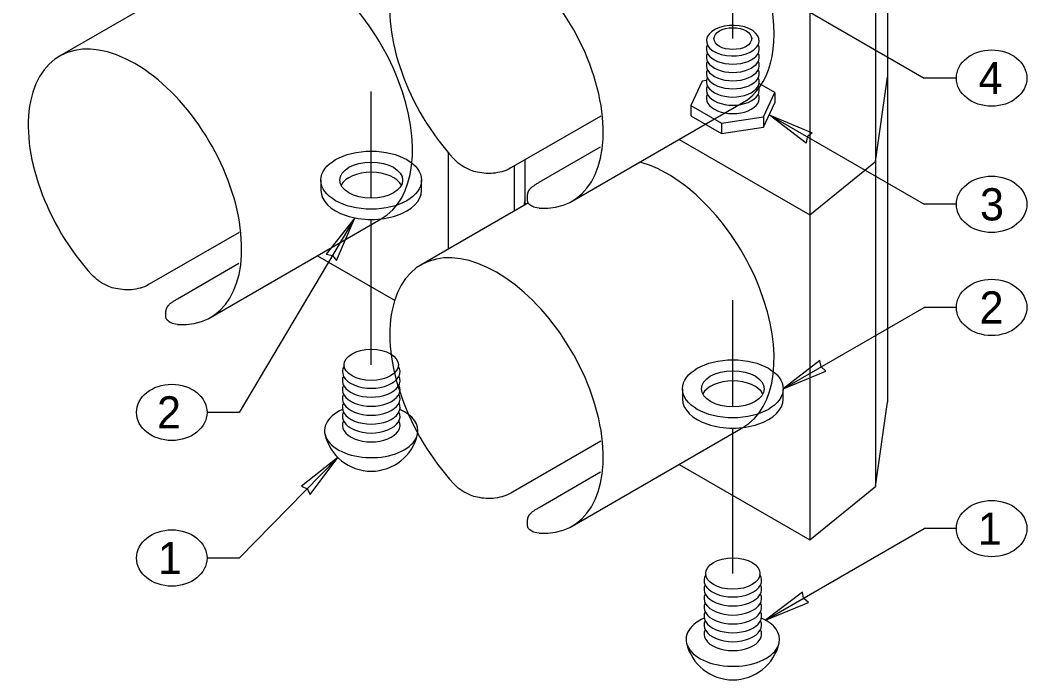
# Model space of a CAD drawing. Extents: x 99862 to 104211, y 98939 to 105076.
# Drawn here: x 101813 to 102313, y 100883 to 101211 of the extents above; entities that cross this region are included whole.
import ezdxf

# ---------------------------------------------------------------- set-up
doc = ezdxf.new("R2010")
doc.units = 0
for name, color, linetype in [('Level 1', 7, 'Continuous'), ('Level 15', 7, 'Continuous'), ('Level 19', 7, 'Continuous'), ('Level 2', 7, 'Continuous'), ('Level 20', 7, 'Continuous'), ('Level 26', 7, 'Continuous'), ('Level 3', 7, 'Continuous')]:
    doc.layers.add(name, color=color, linetype=linetype)

msp = doc.modelspace()

# ---------------------------------------------------------------- linework, layer by layer
at = {"layer": 'Level 1'}
for centre in [(101987.57, 101010.53), (102167.22, 100906.81)]:
    msp.add_arc(centre, 23.6, 192.7466, 347.2534, dxfattribs=at)
for centre in [(101987.57, 101039.77), (102167.22, 100936.05)]:
    msp.add_ellipse(centre, major_axis=(-13.49, 0), ratio=0.57735, dxfattribs=at)
for centre, major_axis, start_param, end_param in [((101987.57, 101036.43), (14.31, 0), 2.795302, 6.629476), ((101987.57, 101031.98), (14.31, 0), 2.86885, 6.555928), ((101987.57, 101027.44), (14.31, 0), 2.86338, 6.561398), ((101987.57, 101022.99), (14.31, 0), 2.86885, 6.555928), ((101987.57, 101007.06), (23.21, 0), 2.229419, 6.153315), ((101987.57, 101018.63), (14.31, 0), 2.874311, 6.550467), ((101987.57, 101007.06), (23.21, 0), 6.153315, 7.195359), ((101987.57, 101014.18), (14.31, 0), 2.86885, 6.555928), ((101987.57, 101009.73), (14.31, 0), 2.86885, 6.555928), ((102167.22, 100932.71), (14.31, 0), 2.795302, 6.629476), ((102167.22, 100928.26), (14.31, 0), 2.86885, 6.555928), ((102167.22, 100923.72), (14.31, 0), 2.86338, 6.561398), ((102167.22, 100919.27), (14.31, 0), 2.86885, 6.555928), ((102167.22, 100914.91), (14.31, 0), 2.874311, 6.550467), ((102167.22, 100903.34), (23.21, 0), 2.229419, 6.153315), ((102167.22, 100910.46), (14.31, 0), 2.86885, 6.555928), ((102167.22, 100903.34), (23.21, 0), 6.153315, 7.195359), ((102167.22, 100906.01), (14.31, 0), 2.86885, 6.555928)]:
    msp.add_ellipse(centre, major_axis=major_axis, ratio=0.57735, start_param=start_param, end_param=end_param, dxfattribs=at)
at = {"layer": 'Level 15'}
for p, q in [((102184.9, 101227.03), (102262.3, 101182.34)), ((102167.23, 101201.93), (102167.23, 101217.7)), ((102278.3, 101182.34), (102262.3, 101182.34)), ((101987.57, 101122.57), (101987.57, 101175.69)), ((102185.33, 101164.02), (102262.3, 101119.58)), ((102278.3, 101119.58), (102262.3, 101119.58)), ((101979.46, 101112.84), (101921.98, 101016.17)), ((101987.57, 101039.77), (101987.57, 101112.06)), ((102167.22, 101018.86), (102167.22, 101071.97)), ((102192.22, 101027.88), (102262.3, 101068.34)), ((102278.3, 101068.34), (102262.3, 101068.34)), ((101921.98, 101016.17), (101905.98, 101016.17)), ((102167.22, 100936.05), (102167.22, 101008.34)), ((101971.03, 100993.7), (101921.98, 100943.78)), ((102183.5, 100912.89), (102262.3, 100958.39)), ((102278.3, 100958.39), (102262.3, 100958.39)), ((101921.98, 100943.78), (101905.98, 100943.78))]:
    msp.add_line(p, q, dxfattribs=at)
for points in [[(102185.33, 101164.02), (102206.6, 101155.19), (102204.19, 101153.13), (102203.61, 101150.02)], [(101979.46, 101112.84), (101965.22, 101094.74), (101968.33, 101094.13), (101970.36, 101091.69)], [(102192.22, 101027.88), (102213.48, 101036.71), (102211.08, 101038.76), (102210.5, 101041.88)], [(101971.03, 100993.7), (101952.9, 100979.51), (101955.77, 100978.17), (101957.16, 100975.32)], [(102183.5, 100912.89), (102204.77, 100921.72), (102202.36, 100923.78), (102201.78, 100926.89)]]:
    msp.add_lwpolyline(points, close=True, dxfattribs=at)
at = {"layer": 'Level 19'}
for p, q in [((102238.16, 101140.84), (102244.04, 101182.83)), ((102205.4, 101114.35), (102238.16, 101140.84)), ((102063.56, 101119.06), (102063.98, 101122.03)), ((102238.16, 100979.28), (102244.04, 101021.28)), ((102205.4, 100952.79), (102238.16, 100979.28))]:
    msp.add_line(p, q, dxfattribs=at)
at = {"layer": 'Level 2'}
for p, q in [((102182.53, 101163.08), (102188.13, 101175.16)), ((102146.31, 101168.69), (102161.62, 101159.85)), ((102161.62, 101159.85), (102182.53, 101163.08)), ((102182.53, 101163.08), (102182.53, 101157.98)), ((102161.62, 101159.85), (102161.62, 101154.74)), ((101962.57, 101131.59), (101962.57, 101126.49)), ((102012.57, 101126.49), (102012.57, 101131.59)), ((102142.22, 101027.88), (102142.22, 101022.77)), ((102192.22, 101022.77), (102192.22, 101027.88))]:
    msp.add_line(p, q, dxfattribs=at)
for centre, major_axis in [((102167.22, 101201.93), (9.38, 0)), ((101987.57, 101131.59), (25, 0)), ((101987.57, 101131.59), (15.62, 0)), ((102167.22, 101027.88), (25, 0)), ((102167.22, 101027.88), (15.62, 0))]:
    msp.add_ellipse(centre, major_axis=major_axis, ratio=0.57735, dxfattribs=at)
for centre, major_axis, start_param, end_param in [((102167.22, 101196.82), (-13.12, 0), 6.010442, 9.697521), ((102167.22, 101192.74), (-13.12, 0), 6.010442, 9.697521), ((102167.22, 101188.58), (-13.12, 0), 6.004973, 9.70299), ((102167.22, 101180.49), (-13.12, 0), 6.010442, 9.697521), ((102167.22, 101184.58), (-13.12, 0), 6.015903, 9.69206), ((102167.22, 101176.41), (-13.12, 0), 6.010442, 9.697521), ((101987.57, 101126.49), (-15.62, 0), 3.428349, 5.996429), ((101987.57, 101126.49), (-25, 0), 0, 3.141593), ((102167.22, 101022.77), (-15.62, 0), 3.428349, 5.996429), ((102167.22, 101022.77), (-25, 0), 0, 3.141593)]:
    msp.add_ellipse(centre, major_axis=major_axis, ratio=0.57735, start_param=start_param, end_param=end_param, dxfattribs=at)
at = {"layer": 'Level 20'}
for centre in [(102295.8, 101182.34), (102295.8, 101119.58), (102295.8, 101068.34), (101888.48, 101016.17), (102295.8, 100958.39), (101888.48, 100943.78)]:
    msp.add_ellipse(centre, major_axis=(-17.5, 0), ratio=0.8, dxfattribs=at)
at = {"layer": 'Level 26'}
for p, q in [((102244.04, 101332.12), (102244.04, 101182.83)), ((102238.16, 101294.83), (102238.16, 101140.84)), ((102205.4, 101275.91), (102205.4, 101114.35)), ((101886.04, 101224.01), (101832.69, 101193.21)), ((102244.04, 101182.83), (102244.04, 101021.28)), ((102087.33, 101121.14), (102172.19, 101170.13)), ((102101.6, 101163.46), (102056.91, 101137.65)), ((102071.05, 101130.52), (102101.5, 101148.1)), ((102140.48, 101151.83), (102205.4, 101114.35)), ((102140.48, 101151.83), (102205.4, 101114.35)), ((102025.75, 101145.44), (102025.75, 101097.24)), ((102058.52, 101138.58), (102058.52, 101116.15)), ((102063.98, 101119.3), (102063.98, 101141.73)), ((102238.16, 101140.84), (102238.16, 100979.28)), ((102065.19, 101122.16), (102065.19, 101123.21)), ((102065.69, 101120.29), (102012.33, 101089.49)), ((101907.69, 101063.3), (101992.54, 101112.29)), ((102205.4, 101114.35), (102205.4, 100952.79)), ((101921.96, 101105.62), (101877.26, 101079.81)), ((101960.84, 101093.99), (101999.16, 101071.86)), ((101891.4, 101072.68), (101921.86, 101090.26)), ((101885.54, 101064.32), (101885.54, 101065.37)), ((102087.33, 100959.58), (102172.19, 101008.57)), ((102101.6, 101001.9), (102056.91, 100976.09)), ((102140.48, 100990.27), (102205.4, 100952.79)), ((102071.05, 100968.96), (102101.5, 100986.54)), ((102065.19, 100960.6), (102065.19, 100961.65))]:
    msp.add_line(p, q, dxfattribs=at)
for centre, start_param, end_param in [((102134.69, 101235.08), 0, 3.141593), ((102049.83, 101186.09), 5.909304, 11.369456), ((101955.04, 101177.25), 0, 2.616954), ((101870.19, 101128.26), 5.909304, 11.369456), ((102134.69, 101073.53), 0, 2.616954), ((102049.83, 101024.54), 5.909304, 11.369456)]:
    msp.add_ellipse(centre, major_axis=(37.5, -64.95), ratio=0.57735, start_param=start_param, end_param=end_param, dxfattribs=at)
for points, degree in [([(102056.91, 101137.65), (102054.99, 101136.55), (102052.73, 101135.74), (102047.77, 101134.85), (102045.08, 101134.79), (102039.82, 101135.51), (102037.19, 101136.32), (102032.49, 101138.72), (102030.37, 101140.32), (102028.62, 101142.22)], 3), ([(102065.19, 101123.2), (102065.19, 101125.53), (102067.3, 101128.35), (102071.05, 101130.52)], 2), ([(102071.05, 101117.72), (102069.3, 101117.85), (102067.86, 101118.3), (102065.81, 101119.79), (102065.24, 101120.82), (102065.19, 101122.05), (102065.19, 101122.08), (102065.19, 101122.12)], 3), ([(101877.26, 101079.81), (101875.35, 101078.71), (101873.08, 101077.9), (101868.12, 101077.01), (101865.44, 101076.95), (101860.17, 101077.67), (101857.55, 101078.48), (101852.84, 101080.88), (101850.73, 101082.48), (101848.97, 101084.38)], 3), ([(101885.54, 101065.36), (101885.54, 101067.69), (101887.65, 101070.51), (101891.4, 101072.68)], 2), ([(101891.4, 101059.88), (101889.65, 101060.01), (101888.21, 101060.46), (101886.16, 101061.95), (101885.59, 101062.99), (101885.54, 101064.21), (101885.54, 101064.24), (101885.54, 101064.28)], 3), ([(102056.91, 100976.09), (102054.99, 100974.99), (102052.73, 100974.18), (102047.77, 100973.3), (102045.08, 100973.23), (102039.82, 100973.95), (102037.19, 100974.76), (102032.49, 100977.16), (102030.37, 100978.77), (102028.62, 100980.66)], 3), ([(102065.19, 100961.64), (102065.19, 100963.97), (102067.3, 100966.79), (102071.05, 100968.96)], 2), ([(102071.05, 100956.16), (102069.3, 100956.29), (102067.86, 100956.74), (102065.81, 100958.23), (102065.24, 100959.27), (102065.19, 100960.49), (102065.19, 100960.53), (102065.19, 100960.56)], 3)]:
    msp.add_open_spline(points, degree=degree, dxfattribs=at)
at = {"layer": 'Level 3'}
for p, q in [((102151.91, 101180.76), (102146.31, 101168.69)), ((102154.14, 101181.1), (102151.91, 101180.76)), ((102188.13, 101175.16), (102180.27, 101179.7)), ((102188.13, 101175.16), (102188.13, 101170.05)), ((102146.31, 101168.69), (102146.31, 101163.58)), ((102182.53, 101157.98), (102188.13, 101170.05)), ((102146.31, 101163.58), (102161.62, 101154.74)), ((102161.62, 101154.74), (102182.53, 101157.98))]:
    msp.add_line(p, q, dxfattribs=at)
for centre, start_param, end_param in [((102167.22, 101200.91), 5.832326, 12.115165), ((102167.22, 101172.24), 6.00421, 9.703753)]:
    msp.add_ellipse(centre, major_axis=(-13.12, 0), ratio=0.57735, start_param=start_param, end_param=end_param, dxfattribs=at)

# ---------------------------------------------------------------- texts
at = {"layer": 'Level 20'}
for s, p in [('4', (102289.29, 101174.35)), ('3', (102290.02, 101111.58)), ('2', (102289.81, 101060.34)), ('2', (101881.16, 101008.17)), ('1', (102288.93, 100950.39)), ('1', (101881.61, 100935.78))]:
    msp.add_text(s, height=16, dxfattribs=at).set_placement(p)

doc.saveas('drawing.dxf')
